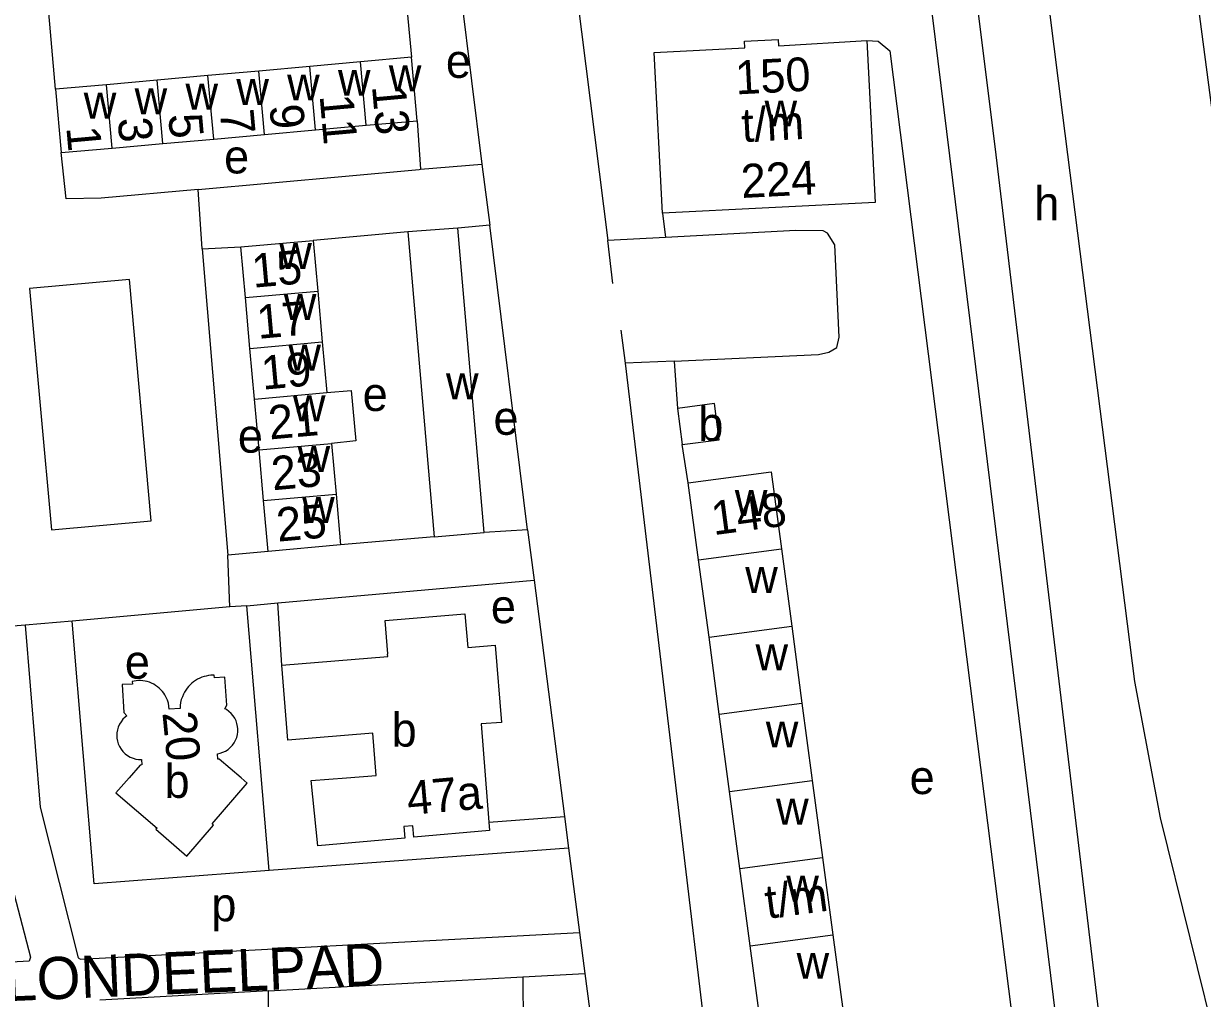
# Model space of a CAD drawing. Extents: x 159294 to 161936, y 384538 to 386517.
# Drawn here: x 161074.2 to 161214, y 385473.9 to 385589.4 of the extents above; entities that cross this region are included whole.
import ezdxf

# ---------------------------------------------------------------- set-up
doc = ezdxf.new("R2010")
doc.units = 0
for name, color, linetype in [('BLT_Basislijn', 7, 'Continuous'), ('BLT_Bebouwing', 7, 'Continuous'), ('BLT_Centroide', 7, 'Continuous'), ('BLT_Huisnummer', 7, 'Continuous'), ('BLT_Huisnummer_ tussenligend', 7, 'Continuous'), ('BLT_Huisnummer_reeks', 7, 'Continuous'), ('BLT_Onderverdeling_panden', 7, 'Continuous'), ('BLT_Straatnaam', 7, 'Continuous')]:
    doc.layers.add(name, color=color, linetype=linetype)

msp = doc.modelspace()

# ---------------------------------------------------------------- linework, layer by layer
at = {"layer": 'BLT_Basislijn'}
for p, q in [((161119.15, 385596.74), (161120.18, 385585.45)), ((161125.48, 385597.39), (161128.54, 385572.76)), ((161077.98, 385581.66), (161077, 385592.83)), ((161120.85, 385577.93), (161121.27, 385572.17)), ((161121.27, 385572.17), (161128.54, 385572.76)), ((161128.54, 385572.76), (161129.47, 385565.53)), ((161095.39, 385562.73), (161094.89, 385569.78)), ((161149.94, 385566.95), (161150.29, 385564.07)), ((161119.77, 385564.75), (161108.53, 385563.74)), ((161129.47, 385565.53), (161125.7, 385565.19)), ((161133.96, 385529.42), (161129.47, 385565.53)), ((161095.39, 385562.73), (161099.95, 385562.96)), ((161150.29, 385564.07), (161143.46, 385563.72)), ((161144.06, 385558.61), (161143.46, 385563.72)), ((161095.39, 385562.73), (161098.43, 385526.4)), ((161145.01, 385553.11), (161145.51, 385549.17)), ((161151.34, 385549.42), (161145.51, 385549.17)), ((161151.34, 385549.42), (161151.75, 385543.82)), ((161153, 385534.99), (161152.3, 385539.55)), ((161133.96, 385529.42), (161128.8, 385529.09)), ((161133.96, 385529.42), (161134.74, 385523.46)), ((161122.87, 385528.59), (161111.78, 385527.64)), ((161103.2, 385526.86), (161098.43, 385526.4)), ((161098.67, 385520.28), (161098.43, 385526.4)), ((161104.33, 385520.77), (161134.74, 385523.46)), ((161134.74, 385523.46), (161138.32, 385495.44)), ((161098.67, 385520.28), (161079.96, 385518.6)), ((161100.66, 385520.42), (161098.67, 385520.28)), ((161100.66, 385520.42), (161104.33, 385520.77)), ((161103.3, 385489.01), (161100.66, 385520.42)), ((161104.8, 385513.38), (161104.33, 385520.77)), ((161079.96, 385518.6), (161074.39, 385518.1)), ((161074.39, 385518.1), (161069.86, 385517.76)), ((161129.37, 385494.74), (161138.32, 385495.44)), ((161138.32, 385495.44), (161138.81, 385491.68)), ((161138.81, 385491.68), (161103.3, 385489.01)), ((161138.81, 385491.68), (161140.11, 385481.68)), ((161140.11, 385481.68), (161140.75, 385476.81)), ((161103.22, 385474.77), (161133.38, 385476.41)), ((161133.38, 385476.41), (161140.75, 385476.81)), ((161133.38, 385476.41), (161133.45, 385466.53)), ((161103.22, 385474.77), (161083.24, 385473.67)), ((161103.23, 385464.92), (161103.22, 385474.77))]:
    msp.add_line(p, q, dxfattribs=at)
for points in [[(161156.38, 385727.15), (161122.79, 385722.77), (161121.26, 385722.38), (161119.6, 385721.43), (161118.96, 385720.63), (161118.19, 385717.74), (161119.06, 385710.19), (161119.38, 385709.55), (161123.36, 385709.84), (161125.27, 385708.12), (161126.28, 385700), (161143.46, 385563.72)], [(161213.78, 385374.6), (161206.23, 385431.72), (161203.35, 385458.32), (161189.41, 385574.89), (161181.39, 385638.92), (161175.91, 385657.52), (161173.38, 385676.85), (161174.6, 385690.83), (161171.91, 385710.42), (161170.27, 385717.48)], [(161188.79, 385713.22), (161193.98, 385676.16), (161190.53, 385639.06), (161191.21, 385627.46), (161197.4, 385578.59), (161205.9, 385511.45)], [(161173.01, 385649.28), (161176.28, 385633.86), (161179.2, 385612.61), (161198.67, 385454.44)], [(161242.47, 385371.34), (161208.94, 385626.35)], [(161174.18, 385587.42), (161175.54, 385587.35), (161176.91, 385586.22), (161193.88, 385452.19), (161197.6, 385425.09)], [(161094.89, 385569.78), (161083.39, 385568.74), (161079.23, 385568.68), (161078.66, 385574.14)], [(161094.89, 385569.78), (161121.1, 385572.16), (161121.27, 385572.17)], [(161151.34, 385549.42), (161168.45, 385550.21), (161169.66, 385550.47), (161170.61, 385551.04), (161170.9, 385552.28), (161170.4, 385563.22), (161169.53, 385564.58), (161169.02, 385564.86), (161165.78, 385564.9), (161150.29, 385564.07)], [(161074.91, 385558.02), (161077.51, 385529.42), (161089.34, 385530.49), (161086.74, 385559.1), (161074.91, 385558.02)], [(161145.51, 385549.17), (161161.78, 385413), (161163.98, 385385.95), (161168.62, 385386.16), (161169.69, 385387.28), (161170.61, 385390.69), (161171.9, 385391.23)], [(161103.3, 385489.01), (161082.57, 385487.46), (161079.96, 385518.6)], [(161074.39, 385518.1), (161076.15, 385496.53), (161080.67, 385478.66), (161080.93, 385478.5), (161140.11, 385481.68)], [(161205.9, 385511.45), (161208.96, 385495.29), (161219.52, 385452.58), (161226.22, 385425.48), (161233.64, 385370.88)], [(161037.11, 385489.81), (161071.3, 385492.86), (161075.01, 385478.75), (161074.85, 385478.28), (161037.9, 385476.23)], [(161140.75, 385476.81), (161143.45, 385456.45), (161143.41, 385454.46)]]:
    msp.add_lwpolyline(points, dxfattribs=at)
at = {"layer": 'BLT_Bebouwing'}
for p, q in [((161120.18, 385585.45), (161114.15, 385584.91)), ((161120.85, 385577.93), (161120.18, 385585.45)), ((161108.12, 385584.36), (161102.09, 385583.82)), ((161114.15, 385584.91), (161108.12, 385584.36)), ((161090.04, 385582.74), (161084.01, 385582.2)), ((161096.06, 385583.28), (161090.04, 385582.74)), ((161102.09, 385583.82), (161096.06, 385583.28)), ((161084.01, 385582.2), (161077.98, 385581.66)), ((161077.98, 385581.66), (161078.66, 385574.14)), ((161108.8, 385576.85), (161114.82, 385577.39)), ((161114.82, 385577.39), (161120.85, 385577.93)), ((161090.71, 385575.22), (161096.74, 385575.76)), ((161096.74, 385575.76), (161102.77, 385576.3)), ((161102.77, 385576.3), (161108.8, 385576.85)), ((161078.66, 385574.14), (161084.68, 385574.68)), ((161084.68, 385574.68), (161090.71, 385575.22)), ((161125.7, 385565.19), (161119.77, 385564.75)), ((161119.77, 385564.75), (161122.87, 385528.59)), ((161128.8, 385529.09), (161125.7, 385565.19)), ((161099.95, 385562.96), (161108.53, 385563.74)), ((161100.49, 385556.95), (161099.95, 385562.96)), ((161108.53, 385563.74), (161109.07, 385557.72)), ((161109.07, 385557.72), (161109.61, 385551.71)), ((161101.03, 385550.93), (161100.49, 385556.95)), ((161109.61, 385551.71), (161110.15, 385545.69)), ((161101.58, 385544.92), (161101.03, 385550.93)), ((161102.12, 385538.9), (161101.58, 385544.92)), ((161151.75, 385543.82), (161152.3, 385539.55)), ((161110.7, 385539.67), (161111.24, 385533.66)), ((161102.66, 385532.88), (161102.12, 385538.9)), ((161154.24, 385525.85), (161153, 385534.99)), ((161111.24, 385533.66), (161111.78, 385527.64)), ((161103.2, 385526.86), (161102.66, 385532.88)), ((161122.87, 385528.59), (161128.8, 385529.09)), ((161111.78, 385527.64), (161103.2, 385526.86)), ((161164.05, 385527.16), (161165.27, 385518.01)), ((161155.47, 385516.7), (161154.24, 385525.85)), ((161165.27, 385518.01), (161166.49, 385508.86)), ((161156.69, 385507.55), (161155.47, 385516.7)), ((161092.76, 385508.23), (161091.47, 385508.17)), ((161157.91, 385498.4), (161156.69, 385507.55)), ((161167.7, 385499.71), (161168.92, 385490.56)), ((161159.13, 385489.25), (161157.91, 385498.4)), ((161168.92, 385490.56), (161170.14, 385481.41)), ((161160.35, 385480.1), (161159.13, 385489.25)), ((161170.14, 385481.41), (161171.36, 385472.26)), ((161161.57, 385470.95), (161160.35, 385480.1))]:
    msp.add_line(p, q, dxfattribs=at)
for points in [[(161149.94, 385566.95), (161148.96, 385586), (161159.71, 385586.55), (161159.67, 385587.35), (161163.65, 385587.55), (161163.69, 385586.82), (161174.18, 385587.42)], [(161174.18, 385587.42), (161175.16, 385568.25), (161149.94, 385566.95)], [(161110.15, 385545.69), (161113.05, 385545.95), (161113.59, 385539.97), (161110.7, 385539.67)], [(161152.3, 385539.55), (161156.67, 385540.11), (161156.12, 385544.38), (161151.75, 385543.82)], [(161153, 385534.99), (161162.84, 385536.3), (161164.05, 385527.16)], [(161104.8, 385513.38), (161117.37, 385514.4), (161117.35, 385514.69), (161117.39, 385514.7), (161117.06, 385518.68), (161126.53, 385519.46), (161126.86, 385515.47), (161130.12, 385515.74), (161130.86, 385506.59), (161128.46, 385506.4), (161128.93, 385500.33), (161129.37, 385494.74)], [(161129.37, 385494.74), (161129.45, 385493.76), (161120.48, 385492.97), (161120.35, 385494.34), (161119.27, 385494.25), (161119.4, 385492.86), (161109.07, 385491.95), (161108.3, 385499.69), (161112.49, 385500), (161116.02, 385500.29), (161115.62, 385505.3), (161105.53, 385504.48), (161104.8, 385513.38)], [(161090.95, 385509.85), (161090.81, 385510.06), (161090.65, 385510.26), (161090.48, 385510.46), (161090.28, 385510.64), (161090.08, 385510.82), (161089.85, 385510.97), (161089.62, 385511.11), (161089.37, 385511.23), (161089.12, 385511.34), (161088.86, 385511.42), (161088.6, 385511.48), (161088.34, 385511.52), (161088.07, 385511.54), (161087.82, 385511.55), (161087.56, 385511.53), (161087.08, 385511.45), (161087.12, 385511.13), (161085.88, 385511.07), (161086.09, 385507.78), (161086.43, 385507.37)], [(161098.06, 385508.21), (161098.28, 385508.64), (161098.07, 385511.95), (161096.83, 385511.89), (161096.8, 385512.19), (161096.38, 385512.17), (161096.11, 385512.14), (161095.85, 385512.09), (161095.59, 385512.02), (161095.33, 385511.94), (161095.08, 385511.83), (161094.83, 385511.71), (161094.59, 385511.56), (161094.36, 385511.41), (161094.14, 385511.23), (161093.94, 385511.04), (161093.75, 385510.84), (161093.58, 385510.63), (161093.42, 385510.41), (161093.28, 385510.18), (161093.16, 385509.95)], [(161091.47, 385508.17), (161091.43, 385508.52), (161091.36, 385508.87), (161091.26, 385509.21), (161091.12, 385509.54), (161090.95, 385509.85)], [(161093.16, 385509.95), (161093.02, 385509.63), (161092.9, 385509.29), (161092.82, 385508.94), (161092.78, 385508.59), (161092.76, 385508.23)], [(161166.49, 385508.86), (161167.67, 385500), (161167.7, 385499.71)], [(161086.43, 385507.37), (161086.23, 385507.22), (161085.98, 385506.96), (161085.75, 385506.67), (161085.57, 385506.36), (161085.42, 385506.03), (161085.33, 385505.69), (161085.27, 385505.36), (161085.25, 385505.03), (161085.27, 385504.71), (161085.33, 385504.38), (161085.43, 385504.06), (161085.57, 385503.74), (161085.76, 385503.43), (161085.98, 385503.14), (161086.24, 385502.88), (161086.53, 385502.66), (161086.84, 385502.48), (161087.17, 385502.34), (161087.5, 385502.24), (161087.83, 385502.19), (161088.16, 385502.17)], [(161097.2, 385502.86), (161097.52, 385502.93), (161097.83, 385503.04), (161098.14, 385503.18), (161098.44, 385503.37), (161098.71, 385503.6), (161098.96, 385503.87), (161099.17, 385504.16), (161099.34, 385504.48), (161099.47, 385504.81), (161099.56, 385505.15), (161099.6, 385505.48), (161099.6, 385505.81), (161099.57, 385506.12), (161099.5, 385506.44), (161099.39, 385506.76), (161099.24, 385507.08), (161099.05, 385507.37), (161098.81, 385507.65), (161098.55, 385507.89), (161098.25, 385508.1), (161098.06, 385508.21)], [(161088.16, 385502.17), (161088.21, 385501.55), (161088.03, 385501.53), (161086.7, 385500), (161085.15, 385498.23), (161090.02, 385494.05), (161089.88, 385493.91), (161093.56, 385490.73), (161096.71, 385494.41), (161096.55, 385494.56), (161100.71, 385499.39), (161100, 385500), (161097.38, 385502.22), (161097.22, 385502.24), (161097.2, 385502.86)]]:
    msp.add_lwpolyline(points, dxfattribs=at)
at = {"layer": 'BLT_Onderverdeling_panden'}
for p, q in [((161108.8, 385576.85), (161108.12, 385584.36)), ((161114.82, 385577.39), (161114.15, 385584.91)), ((161090.71, 385575.22), (161090.04, 385582.74)), ((161096.74, 385575.76), (161096.06, 385583.28)), ((161102.77, 385576.3), (161102.09, 385583.82)), ((161084.68, 385574.68), (161084.01, 385582.2)), ((161100.49, 385556.95), (161109.07, 385557.72)), ((161101.03, 385550.93), (161109.61, 385551.71)), ((161101.58, 385544.92), (161110.15, 385545.69)), ((161102.12, 385538.9), (161110.7, 385539.67)), ((161102.66, 385532.88), (161111.24, 385533.66)), ((161154.24, 385525.85), (161164.05, 385527.16)), ((161155.47, 385516.7), (161165.27, 385518.01)), ((161156.69, 385507.55), (161166.49, 385508.86)), ((161157.91, 385498.4), (161167.7, 385499.71)), ((161159.13, 385489.25), (161168.92, 385490.56)), ((161160.35, 385480.1), (161170.14, 385481.41))]:
    msp.add_line(p, q, dxfattribs=at)

# ---------------------------------------------------------------- texts
at = {"layer": 'BLT_Centroide'}
for s, p in [('e', (161124.27, 385583.01)), ('w', (161111.47, 385580.88)), ('w', (161117.5, 385581.42)), ('w', (161099.42, 385579.8)), ('w', (161105.44, 385580.33)), ('w', (161081.33, 385578.17)), ('w', (161087.36, 385578.7)), ('w', (161093.39, 385579.25)), ('w', (161162.05, 385577.25)), ('e', (161097.97, 385571.68)), ('h', (161194.04, 385566.13)), ('w', (161104.51, 385560.34)), ('w', (161105.05, 385554.31)), ('w', (161105.59, 385548.31)), ('w', (161124.28, 385544.91)), ('e', (161114.4, 385543.51)), ('w', (161106.13, 385542.28)), ('e', (161129.91, 385540.69)), ('b', (161154.2, 385539.97)), ('e', (161099.6, 385538.57)), ('w', (161106.68, 385536.28)), ('w', (161158.53, 385531.06)), ('w', (161107.22, 385530.25)), ('w', (161159.76, 385521.94)), ('e', (161129.6, 385518.35)), ('w', (161160.98, 385512.78)), ('e', (161086.2, 385511.77)), ('b', (161117.83, 385503.72)), ('w', (161162.2, 385503.62)), ('b', (161090.91, 385497.64)), ('e', (161179.25, 385498.09)), ('w', (161163.42, 385494.47)), ('w', (161164.63, 385485.34)), ('p', (161096.46, 385483.01)), ('w', (161165.85, 385476.19))]:
    msp.add_text(s, height=4, dxfattribs=at).set_placement(p)
at = {"layer": 'BLT_Huisnummer'}
for s, rotation, p in [('13', 275.1367, (161115.5, 385582.03)), ('9', 275.1367, (161103.34, 385579.73)), ('5', 275.1367, (161091.34, 385578.64)), ('1', 275.1367, (161079.26, 385577.13)), ('15', 5.1499, (161101.43, 385558.12)), ('19', 5.1505, (161102.55, 385546.03)), ('25', 5.1493, (161104.35, 385528.01)), ('20', 275.5473, (161090.65, 385507.74)), ('47a', 5.0524, (161119.81, 385495.6))]:
    msp.add_text(s, height=4, rotation=rotation, dxfattribs=at).set_placement(p)
at = {"layer": 'BLT_Huisnummer_ tussenligend'}
for s, rotation, p in [('11', 275.1367, (161109.29, 385580.9)), ('7', 275.1367, (161097.46, 385579.12)), ('3', 275.1367, (161085.34, 385578.18)), ('17', 5.1499, (161102.02, 385552.06)), ('21', 5.1505, (161103.39, 385540.13)), ('23', 5.1505, (161103.74, 385534.1))]:
    msp.add_text(s, height=4, rotation=rotation, dxfattribs=at).set_placement(p)
at = {"layer": 'BLT_Huisnummer_reeks'}
for s, rotation, p in [('150', 2.9529, (161158.68, 385581.04)), ('t/m', 2.9529, (161159.42, 385575.39)), ('224', 2.9529, (161159.35, 385568.76)), ('148', 7.6134, (161156.01, 385528.78)), ('t/m', 7.615, (161162.38, 385483.29))]:
    msp.add_text(s, height=4, rotation=rotation, dxfattribs=at).set_placement(p)
at = {"layer": 'BLT_Straatnaam'}
msp.add_text('BLONDEELPAD', height=5, rotation=2.4459, dxfattribs=at).set_placement((161067.68, 385473.33))

doc.saveas('drawing.dxf')
